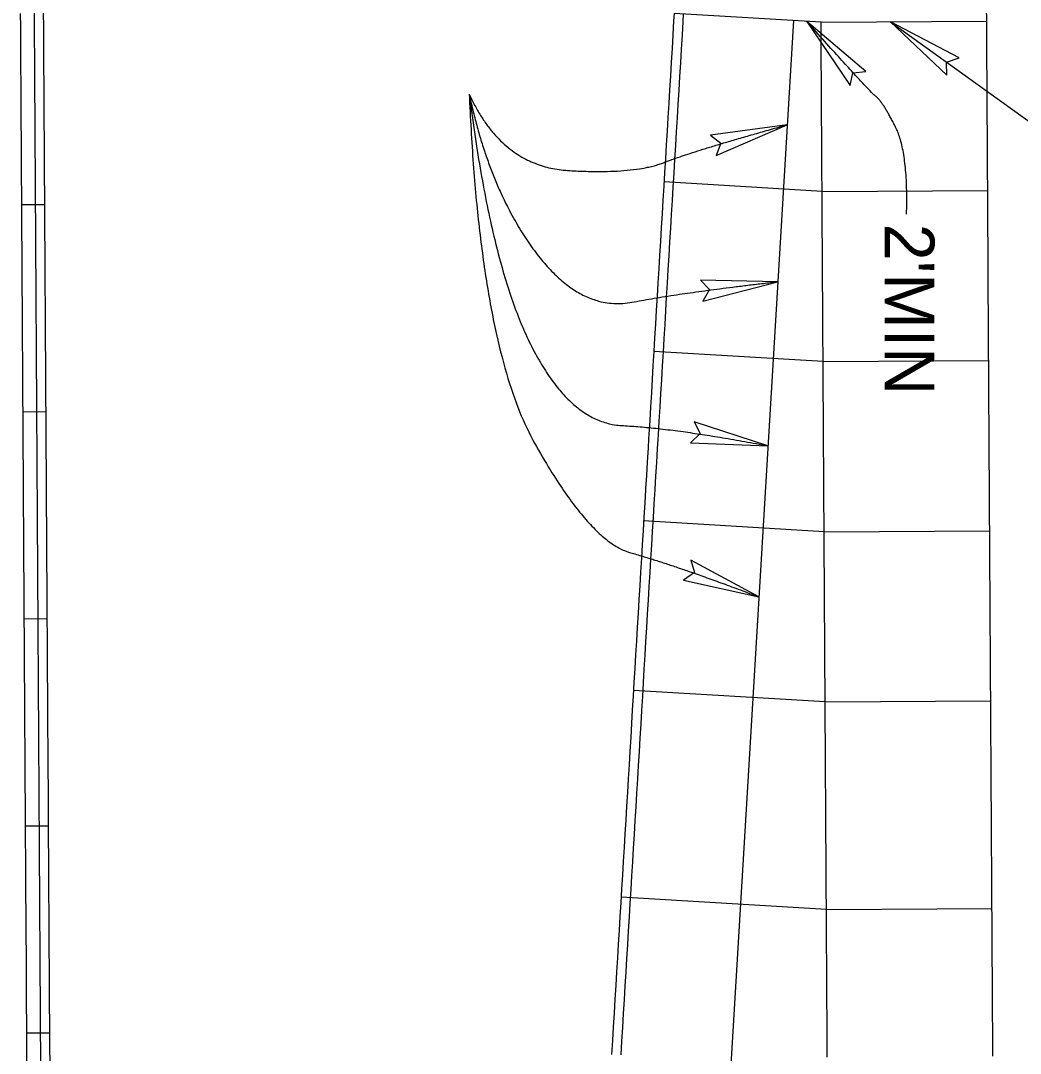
# Model space of a CAD drawing. Extents: x 2145147 to 2158018, y 137519 to 148068.
# Drawn here: x 2150694.3 to 2150766.8, y 145144.1 to 145218.9 of the extents above; entities that cross this region are included whole.
import ezdxf

# ---------------------------------------------------------------- set-up
doc = ezdxf.new("R2010")
doc.units = 0
for name, color, linetype in [('PR_Align_Service_C_Leader', 7, 'Continuous'), ('PR_Arrows', 7, 'Continuous'), ('PR_Dimensions', 7, 'Continuous'), ('PR_Joint_Contraction', 7, 'Continuous'), ('PR_Joint_Isolation', 7, 'Continuous'), ('PR_Joint_Long', 7, 'Continuous'), ('PR_Road_Concrete', 7, 'Continuous')]:
    doc.layers.add(name, color=color, linetype=linetype)

msp = doc.modelspace()

# ---------------------------------------------------------------- linework, layer by layer
at = {"layer": 'PR_Align_Service_C_Leader'}
msp.add_lwpolyline([(2150757.359, 145218.855), (2150790.048, 145195.375), (2150790.048, 145161.067)], dxfattribs=at)
at = {"layer": 'PR_Arrows'}
msp.add_lwpolyline([(2150757.359, 145218.855), (2150761.441, 145215.001), (2150761.409, 145215.946), (2150762.328, 145216.251)], close=True, dxfattribs=at)
at = {"layer": 'PR_Dimensions'}
for points in [[(2150751.293, 145218.887), (2150754.444, 145214.24), (2150754.617, 145215.17), (2150755.58, 145215.269)], [(2150749.875, 145211.399), (2150744.313, 145210.639), (2150745.069, 145210.071), (2150744.73, 145209.164)], [(2150749.193, 145200.035), (2150743.58, 145200.153), (2150744.238, 145199.474), (2150743.762, 145198.631)], [(2150748.479, 145188.142), (2150743.14, 145189.877), (2150743.573, 145189.037), (2150742.874, 145188.367)], [(2150747.822, 145177.202), (2150742.877, 145179.859), (2150743.154, 145178.955), (2150742.346, 145178.421)]]:
    msp.add_lwpolyline(points, close=True, dxfattribs=at)
for points in [[(2150758.521, 145204.92), (2150758.652, 145209.4), (2150756.787, 145213.083), (2150755.846, 145213.795), (2150751.293, 145218.887)], [(2150726.826, 145213.625), (2150729.216, 145208.404), (2150738.69, 145207.785), (2150743.291, 145209.579), (2150749.875, 145211.399)], [(2150726.826, 145213.625), (2150728.331, 145206.59), (2150734.882, 145197.829), (2150742.405, 145199.266), (2150749.193, 145200.035)], [(2150726.826, 145213.625), (2150728.375, 145201.369), (2150734.082, 145189.801), (2150741.765, 145189.418), (2150748.479, 145188.142)], [(2150726.826, 145213.625), (2150727.615, 145195.337), (2150735.577, 145181.204), (2150741.428, 145179.604), (2150747.822, 145177.202)]]:
    msp.add_open_spline(points, degree=2, dxfattribs=at)
at = {"layer": 'PR_Joint_Contraction'}
for p, q in [((2150752.398, 145206.57), (2150740.944, 145207.258)), ((2150752.398, 145206.57), (2150764.398, 145206.642)), ((2150694.412, 145205.615), (2150696.079, 145205.624)), ((2150752.472, 145194.243), (2150740.207, 145194.98)), ((2150752.472, 145194.243), (2150764.472, 145194.316)), ((2150694.503, 145190.615), (2150696.169, 145190.625)), ((2150752.546, 145181.917), (2150739.47, 145182.702)), ((2150752.546, 145181.917), (2150764.546, 145181.989)), ((2150694.594, 145175.615), (2150696.26, 145175.625)), ((2150752.62, 145169.59), (2150738.733, 145170.424)), ((2150752.62, 145169.59), (2150764.62, 145169.662)), ((2150694.684, 145160.616), (2150696.351, 145160.625)), ((2150752.71, 145154.558), (2150737.834, 145155.451)), ((2150752.71, 145154.558), (2150764.71, 145154.63)), ((2150694.775, 145145.616), (2150696.442, 145145.625))]:
    msp.add_line(p, q, dxfattribs=at)
at = {"layer": 'PR_Joint_Isolation'}
for q in [(2150741.677, 145219.464), (2150764.324, 145218.897)]:
    msp.add_line((2150752.324, 145218.825), q, dxfattribs=at)
at = {"layer": 'PR_Joint_Long'}
for points in [[(2150764.774, 145143.939), (2150764.769, 145144.89), (2150764.763, 145145.89), (2150764.757, 145146.89), (2150764.751, 145147.89), (2150764.745, 145148.89), (2150764.739, 145149.89), (2150764.733, 145150.89), (2150764.727, 145151.89), (2150764.721, 145152.89), (2150764.715, 145153.89), (2150764.709, 145154.89), (2150764.703, 145155.89), (2150764.697, 145156.89), (2150764.691, 145157.89), (2150764.685, 145158.89), (2150764.679, 145159.89), (2150764.673, 145160.89), (2150764.667, 145161.89), (2150764.661, 145162.89), (2150764.655, 145163.89), (2150764.649, 145164.89), (2150764.643, 145165.89), (2150764.637, 145166.89), (2150764.631, 145167.89), (2150764.625, 145168.889), (2150764.619, 145169.889), (2150764.612, 145170.889), (2150764.606, 145171.889), (2150764.6, 145172.889), (2150764.594, 145173.889), (2150764.588, 145174.889), (2150764.582, 145175.889), (2150764.576, 145176.889), (2150764.57, 145177.889), (2150764.564, 145178.889), (2150764.558, 145179.889), (2150764.552, 145180.889), (2150764.546, 145181.889), (2150764.54, 145182.889), (2150764.534, 145183.889), (2150764.528, 145184.889), (2150764.522, 145185.889), (2150764.516, 145186.889), (2150764.51, 145187.889), (2150764.504, 145188.889), (2150764.498, 145189.889), (2150764.492, 145190.889), (2150764.486, 145191.889), (2150764.48, 145192.889), (2150764.474, 145193.889), (2150764.468, 145194.889), (2150764.462, 145195.889), (2150764.456, 145196.889), (2150764.45, 145197.889), (2150764.444, 145198.889), (2150764.438, 145199.889), (2150764.432, 145200.889), (2150764.426, 145201.889), (2150764.42, 145202.889), (2150764.416, 145203.65), (2150764.414, 145203.889), (2150764.408, 145204.889), (2150764.402, 145205.889), (2150764.396, 145206.889), (2150764.39, 145207.889), (2150764.384, 145208.889), (2150764.378, 145209.889), (2150764.373, 145210.758), (2150764.372, 145210.889), (2150764.366, 145211.889), (2150764.36, 145212.889), (2150764.354, 145213.889), (2150764.348, 145214.889), (2150764.342, 145215.889), (2150764.336, 145216.889), (2150764.33, 145217.889), (2150764.324, 145218.889), (2150764.324, 145218.897), (2150764.318, 145219.889)], [(2150750.328, 145218.945), (2150715.84, 144644.411)], [(2150752.775, 145143.867), (2150752.769, 145144.818), (2150752.763, 145145.818), (2150752.757, 145146.818), (2150752.751, 145147.818), (2150752.745, 145148.818), (2150752.739, 145149.818), (2150752.733, 145150.818), (2150752.727, 145151.818), (2150752.721, 145152.818), (2150752.715, 145153.818), (2150752.709, 145154.818), (2150752.703, 145155.818), (2150752.697, 145156.818), (2150752.691, 145157.818), (2150752.685, 145158.818), (2150752.679, 145159.818), (2150752.673, 145160.818), (2150752.667, 145161.818), (2150752.661, 145162.817), (2150752.655, 145163.817), (2150752.649, 145164.817), (2150752.643, 145165.817), (2150752.637, 145166.817), (2150752.631, 145167.817), (2150752.625, 145168.817), (2150752.619, 145169.817), (2150752.613, 145170.817), (2150752.607, 145171.817), (2150752.601, 145172.817), (2150752.595, 145173.817), (2150752.589, 145174.817), (2150752.583, 145175.817), (2150752.577, 145176.817), (2150752.571, 145177.817), (2150752.565, 145178.817), (2150752.559, 145179.817), (2150752.553, 145180.817), (2150752.547, 145181.817), (2150752.541, 145182.817), (2150752.535, 145183.817), (2150752.529, 145184.817), (2150752.523, 145185.817), (2150752.517, 145186.817), (2150752.511, 145187.817), (2150752.505, 145188.817), (2150752.499, 145189.817), (2150752.493, 145190.817), (2150752.487, 145191.817), (2150752.481, 145192.817), (2150752.475, 145193.817), (2150752.469, 145194.817), (2150752.463, 145195.817), (2150752.456, 145196.817), (2150752.45, 145197.817), (2150752.444, 145198.817), (2150752.438, 145199.817), (2150752.432, 145200.817), (2150752.426, 145201.817), (2150752.42, 145202.817), (2150752.416, 145203.578), (2150752.414, 145203.817), (2150752.408, 145204.817), (2150752.402, 145205.817), (2150752.396, 145206.817), (2150752.39, 145207.817), (2150752.384, 145208.817), (2150752.378, 145209.817), (2150752.373, 145210.686), (2150752.372, 145210.817), (2150752.366, 145211.817), (2150752.36, 145212.817), (2150752.354, 145213.817), (2150752.348, 145214.817), (2150752.342, 145215.817), (2150752.336, 145216.817), (2150752.33, 145217.817), (2150752.324, 145218.825)]]:
    msp.add_lwpolyline(points, dxfattribs=at)
at = {"layer": 'PR_Road_Concrete'}
for points in [[(2150694.788, 145143.476), (2150694.782, 145144.476), (2150694.776, 145145.476), (2150694.77, 145146.476), (2150694.764, 145147.476), (2150694.758, 145148.475), (2150694.752, 145149.475), (2150694.746, 145150.475), (2150694.74, 145151.475), (2150694.734, 145152.475), (2150694.728, 145153.475), (2150694.721, 145154.475), (2150694.715, 145155.475), (2150694.709, 145156.475), (2150694.703, 145157.475), (2150694.697, 145158.475), (2150694.691, 145159.475), (2150694.685, 145160.475), (2150694.679, 145161.475), (2150694.673, 145162.475), (2150694.667, 145163.475), (2150694.661, 145164.475), (2150694.655, 145165.475), (2150694.649, 145166.475), (2150694.643, 145167.475), (2150694.637, 145168.475), (2150694.631, 145169.475), (2150694.625, 145170.475), (2150694.619, 145171.475), (2150694.613, 145172.475), (2150694.607, 145173.475), (2150694.6, 145174.475), (2150694.594, 145175.475), (2150694.588, 145176.475), (2150694.582, 145177.475), (2150694.576, 145178.475), (2150694.57, 145179.475), (2150694.564, 145180.475), (2150694.558, 145181.475), (2150694.552, 145182.475), (2150694.546, 145183.475), (2150694.54, 145184.475), (2150694.534, 145185.475), (2150694.528, 145186.475), (2150694.526, 145186.805), (2150694.526, 145186.818), (2150694.522, 145187.475), (2150694.516, 145188.475), (2150694.51, 145189.475), (2150694.504, 145190.475), (2150694.498, 145191.475), (2150694.492, 145192.475), (2150694.485, 145193.475), (2150694.479, 145194.475), (2150694.473, 145195.475), (2150694.467, 145196.475), (2150694.461, 145197.475), (2150694.455, 145198.475), (2150694.449, 145199.475), (2150694.443, 145200.475), (2150694.437, 145201.475), (2150694.431, 145202.475), (2150694.425, 145203.474), (2150694.419, 145204.474), (2150694.413, 145205.474), (2150694.407, 145206.474), (2150694.401, 145207.474), (2150694.395, 145208.474), (2150694.389, 145209.474), (2150694.383, 145210.474), (2150694.377, 145211.474), (2150694.37, 145212.474), (2150694.364, 145213.474), (2150694.358, 145214.474), (2150694.352, 145215.474), (2150694.346, 145216.474), (2150694.34, 145217.474), (2150694.334, 145218.474), (2150694.328, 145219.474)], [(2150695.788, 145143.482), (2150695.782, 145144.482), (2150695.776, 145145.482), (2150695.77, 145146.482), (2150695.764, 145147.482), (2150695.758, 145148.482), (2150695.752, 145149.481), (2150695.746, 145150.481), (2150695.74, 145151.481), (2150695.734, 145152.481), (2150695.728, 145153.481), (2150695.721, 145154.481), (2150695.715, 145155.481), (2150695.709, 145156.481), (2150695.703, 145157.481), (2150695.697, 145158.481), (2150695.691, 145159.481), (2150695.685, 145160.481), (2150695.679, 145161.481), (2150695.673, 145162.481), (2150695.667, 145163.481), (2150695.661, 145164.481), (2150695.655, 145165.481), (2150695.649, 145166.481), (2150695.643, 145167.481), (2150695.637, 145168.481), (2150695.631, 145169.481), (2150695.625, 145170.481), (2150695.619, 145171.481), (2150695.613, 145172.481), (2150695.606, 145173.481), (2150695.6, 145174.481), (2150695.594, 145175.481), (2150695.588, 145176.481), (2150695.582, 145177.481), (2150695.576, 145178.481), (2150695.57, 145179.481), (2150695.564, 145180.481), (2150695.558, 145181.481), (2150695.552, 145182.481), (2150695.546, 145183.481), (2150695.54, 145184.481), (2150695.534, 145185.481), (2150695.528, 145186.481), (2150695.526, 145186.811), (2150695.526, 145186.824), (2150695.522, 145187.481), (2150695.516, 145188.481), (2150695.51, 145189.481), (2150695.504, 145190.481), (2150695.498, 145191.481), (2150695.492, 145192.481), (2150695.485, 145193.481), (2150695.479, 145194.481), (2150695.473, 145195.481), (2150695.467, 145196.481), (2150695.461, 145197.481), (2150695.455, 145198.481), (2150695.449, 145199.481), (2150695.443, 145200.481), (2150695.437, 145201.481), (2150695.431, 145202.481), (2150695.425, 145203.481), (2150695.419, 145204.48), (2150695.413, 145205.48), (2150695.407, 145206.48), (2150695.401, 145207.48), (2150695.395, 145208.48), (2150695.389, 145209.48), (2150695.383, 145210.48), (2150695.377, 145211.48), (2150695.37, 145212.48), (2150695.364, 145213.48), (2150695.358, 145214.48), (2150695.352, 145215.48), (2150695.346, 145216.48), (2150695.34, 145217.48), (2150695.334, 145218.48), (2150695.328, 145219.48)], [(2150696.455, 145143.486), (2150696.449, 145144.486), (2150696.443, 145145.486), (2150696.437, 145146.486), (2150696.43, 145147.486), (2150696.424, 145148.486), (2150696.418, 145149.486), (2150696.412, 145150.486), (2150696.406, 145151.485), (2150696.4, 145152.485), (2150696.394, 145153.485), (2150696.388, 145154.485), (2150696.382, 145155.485), (2150696.376, 145156.485), (2150696.37, 145157.485), (2150696.364, 145158.485), (2150696.358, 145159.485), (2150696.352, 145160.485), (2150696.346, 145161.485), (2150696.34, 145162.485), (2150696.334, 145163.485), (2150696.328, 145164.485), (2150696.322, 145165.485), (2150696.316, 145166.485), (2150696.309, 145167.485), (2150696.303, 145168.485), (2150696.297, 145169.485), (2150696.291, 145170.485), (2150696.285, 145171.485), (2150696.279, 145172.485), (2150696.273, 145173.485), (2150696.267, 145174.485), (2150696.261, 145175.485), (2150696.255, 145176.485), (2150696.249, 145177.485), (2150696.243, 145178.485), (2150696.237, 145179.485), (2150696.231, 145180.485), (2150696.225, 145181.485), (2150696.219, 145182.485), (2150696.213, 145183.485), (2150696.207, 145184.485), (2150696.201, 145185.485), (2150696.194, 145186.485), (2150696.192, 145186.815), (2150696.192, 145186.828), (2150696.188, 145187.485), (2150696.182, 145188.485), (2150696.176, 145189.485), (2150696.17, 145190.485), (2150696.164, 145191.485), (2150696.158, 145192.485), (2150696.152, 145193.485), (2150696.146, 145194.485), (2150696.14, 145195.485), (2150696.134, 145196.485), (2150696.128, 145197.485), (2150696.122, 145198.485), (2150696.116, 145199.485), (2150696.11, 145200.485), (2150696.104, 145201.485), (2150696.098, 145202.485), (2150696.092, 145203.485), (2150696.086, 145204.485), (2150696.079, 145205.484), (2150696.073, 145206.484), (2150696.067, 145207.484), (2150696.061, 145208.484), (2150696.055, 145209.484), (2150696.049, 145210.484), (2150696.043, 145211.484), (2150696.037, 145212.484), (2150696.031, 145213.484), (2150696.025, 145214.484), (2150696.019, 145215.484), (2150696.013, 145216.484), (2150696.007, 145217.484), (2150696.001, 145218.484), (2150695.995, 145219.484)], [(2150741.677, 145219.464), (2150741.644, 145218.925), (2150741.584, 145217.927), (2150741.525, 145216.928), (2150741.465, 145215.93), (2150741.405, 145214.932), (2150741.345, 145213.934), (2150741.285, 145212.936), (2150741.225, 145211.937), (2150741.165, 145210.939), (2150741.105, 145209.941), (2150741.045, 145208.943), (2150740.985, 145207.945), (2150740.925, 145206.946), (2150740.865, 145205.948), (2150740.806, 145204.95), (2150740.746, 145203.952), (2150740.686, 145202.954), (2150740.626, 145201.955), (2150740.566, 145200.957), (2150740.506, 145199.959), (2150740.446, 145198.961), (2150740.386, 145197.963), (2150740.326, 145196.964), (2150740.266, 145195.966), (2150740.206, 145194.968), (2150740.146, 145193.97), (2150740.086, 145192.972), (2150740.027, 145191.973), (2150739.967, 145190.975), (2150739.907, 145189.977), (2150739.847, 145188.979), (2150739.827, 145188.65), (2150739.787, 145187.981), (2150739.727, 145186.982), (2150739.667, 145185.984), (2150739.611, 145185.044), (2150739.607, 145184.986), (2150739.547, 145183.988), (2150739.487, 145182.99), (2150739.427, 145181.991), (2150739.367, 145180.993), (2150739.308, 145179.995), (2150739.248, 145178.997), (2150739.188, 145177.998), (2150739.128, 145177), (2150739.068, 145176.002), (2150739.008, 145175.004), (2150738.948, 145174.006), (2150738.888, 145173.007), (2150738.828, 145172.009), (2150738.768, 145171.011), (2150738.708, 145170.013), (2150738.648, 145169.015), (2150738.588, 145168.016), (2150738.529, 145167.018), (2150738.469, 145166.02), (2150738.409, 145165.022), (2150738.349, 145164.024), (2150738.289, 145163.025), (2150738.229, 145162.027), (2150738.169, 145161.029), (2150738.109, 145160.031), (2150738.049, 145159.033), (2150737.989, 145158.034), (2150737.929, 145157.036), (2150737.869, 145156.038), (2150737.81, 145155.04), (2150737.75, 145154.042), (2150737.69, 145153.043), (2150737.63, 145152.045), (2150737.57, 145151.047), (2150737.51, 145150.049), (2150737.45, 145149.051), (2150737.39, 145148.052), (2150737.33, 145147.054), (2150737.27, 145146.056), (2150737.21, 145145.058), (2150737.15, 145144.06)], [(2150742.342, 145219.424), (2150742.31, 145218.885), (2150742.25, 145217.887), (2150742.19, 145216.888), (2150742.13, 145215.89), (2150742.07, 145214.892), (2150742.01, 145213.894), (2150741.95, 145212.896), (2150741.89, 145211.897), (2150741.83, 145210.899), (2150741.771, 145209.901), (2150741.711, 145208.903), (2150741.651, 145207.905), (2150741.591, 145206.906), (2150741.531, 145205.908), (2150741.471, 145204.91), (2150741.411, 145203.912), (2150741.351, 145202.914), (2150741.291, 145201.915), (2150741.231, 145200.917), (2150741.171, 145199.919), (2150741.111, 145198.921), (2150741.052, 145197.923), (2150740.992, 145196.924), (2150740.932, 145195.926), (2150740.872, 145194.928), (2150740.812, 145193.93), (2150740.752, 145192.932), (2150740.692, 145191.933), (2150740.632, 145190.935), (2150740.572, 145189.937), (2150740.512, 145188.939), (2150740.493, 145188.61), (2150740.452, 145187.941), (2150740.392, 145186.942), (2150740.333, 145185.944), (2150740.276, 145185.004), (2150740.273, 145184.946), (2150740.213, 145183.948), (2150740.153, 145182.95), (2150740.093, 145181.951), (2150740.033, 145180.953), (2150739.973, 145179.955), (2150739.913, 145178.957), (2150739.853, 145177.959), (2150739.793, 145176.96), (2150739.733, 145175.962), (2150739.673, 145174.964), (2150739.613, 145173.966), (2150739.554, 145172.968), (2150739.494, 145171.969), (2150739.434, 145170.971), (2150739.374, 145169.973), (2150739.314, 145168.975), (2150739.254, 145167.977), (2150739.194, 145166.978), (2150739.134, 145165.98), (2150739.074, 145164.982), (2150739.014, 145163.984), (2150738.954, 145162.986), (2150738.894, 145161.987), (2150738.835, 145160.989), (2150738.775, 145159.991), (2150738.715, 145158.993), (2150738.655, 145157.994), (2150738.595, 145156.996), (2150738.535, 145155.998), (2150738.475, 145155), (2150738.415, 145154.002), (2150738.355, 145153.003), (2150738.295, 145152.005), (2150738.235, 145151.007), (2150738.175, 145150.009), (2150738.115, 145149.011), (2150738.056, 145148.012), (2150737.996, 145147.014), (2150737.936, 145146.016), (2150737.876, 145145.018), (2150737.816, 145144.02)]]:
    msp.add_lwpolyline(points, dxfattribs=at)

# ---------------------------------------------------------------- texts
at = {"layer": 'PR_Dimensions'}
msp.add_text("2'MIN", height=3.6, rotation=269.99961, dxfattribs=at).set_placement((2150756.938, 145204.233))

doc.saveas('drawing.dxf')
